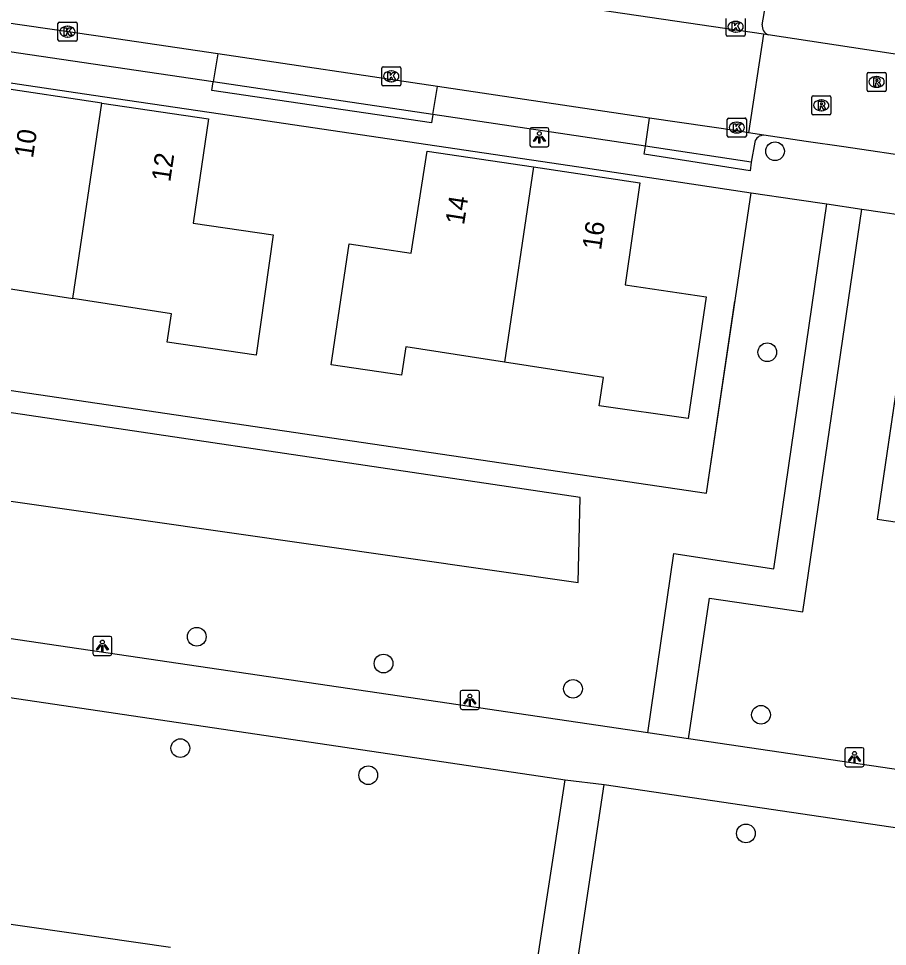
# Model space of a CAD drawing. Extents: x 164150 to 165261, y 382513 to 383432.
# Drawn here: x 164377.35 to 164422.79, y 383245.45 to 383293.97 of the extents above; entities that cross this region are included whole.
import ezdxf

# ---------------------------------------------------------------- set-up
doc = ezdxf.new("R2010")
doc.units = 0
for name, color, linetype in [('IMGEO_Boom', 7, 'Continuous'), ('IMGEO_Fietspad_gesloten', 7, 'Continuous'), ('IMGEO_Greppel_droge_sloot', 7, 'Continuous'), ('IMGEO_Groenvoorziening', 7, 'Continuous'), ('IMGEO_Hek', 7, 'Continuous'), ('IMGEO_Kolk', 7, 'Continuous'), ('IMGEO_Lichtpunt', 7, 'Continuous'), ('IMGEO_Pand', 7, 'Continuous'), ('IMGEO_Pand_nummerreeks', 7, 'Continuous'), ('IMGEO_Rijbaan_lokaal_open', 7, 'Continuous'), ('IMGEO_Rioolput', 7, 'Continuous'), ('IMGEO_Voetpad_gesloten', 7, 'Continuous'), ('IMGEO_Voetpad_open', 7, 'Continuous')]:
    doc.layers.add(name, color=color, linetype=linetype)

msp = doc.modelspace()

# ---------------------------------------------------------------- linework, layer by layer
at = {"layer": 'IMGEO_Boom'}
for centre in [(164416.91, 383287.031), (164416.506, 383276.521), (164386.67, 383261.645), (164396.438, 383260.244), (164406.346, 383258.921), (164416.177, 383257.562), (164385.811, 383255.821), (164395.639, 383254.405), (164415.388, 383251.362)]:
    msp.add_circle(centre, 0.489, dxfattribs=at)
at = {"layer": 'IMGEO_Fietspad_gesloten'}
for points in [[(164324.331, 383266.264), (164405.939, 383254.161)], [(164410.253, 383256.618), (164363.243, 383263.551)], [(164412.392, 383256.302), (164410.253, 383256.618)], [(164469.921, 383247.818), (164412.392, 383256.302)], [(164405.939, 383254.161), (164407.972, 383253.915)], [(164407.972, 383253.915), (164472.414, 383244.404)]]:
    msp.add_lwpolyline(points, dxfattribs=at)
at = {"layer": 'IMGEO_Greppel_droge_sloot'}
msp.add_lwpolyline([(164369.89, 383269.745), (164406.61, 383264.48), (164406.724, 383268.924), (164370.391, 383274.325)], dxfattribs=at)
at = {"layer": 'IMGEO_Groenvoorziening'}
for points in [[(164370.46, 383291.569), (164368.108, 383275.835), (164413.32, 383269.151), (164415.655, 383284.854)], [(164424.578, 383283.554), (164422.255, 383267.801), (164467.471, 383261.119), (164469.81, 383276.81)]]:
    msp.add_lwpolyline(points, dxfattribs=at)
at = {"layer": 'IMGEO_Hek'}
for points in [[(164369.61, 383285.882), (164368.108, 383275.835), (164413.32, 383269.151), (164414.814, 383279.195)], [(164423.736, 383277.843), (164422.255, 383267.801), (164467.471, 383261.119), (164468.968, 383271.158)]]:
    msp.add_lwpolyline(points, dxfattribs=at)
at = {"layer": 'IMGEO_Kolk'}
for p, q in [((164379.413, 383292.858), (164379.413, 383293.71)), ((164379.488, 383293.784), (164380.34, 383293.784)), ((164379.901, 383293.564), (164379.926, 383293.564)), ((164380.414, 383293.71), (164380.414, 383292.858)), ((164414.351, 383293.118), (164414.351, 383293.97)), ((164414.839, 383293.824), (164414.864, 383293.824)), ((164415.352, 383293.97), (164415.352, 383293.118)), ((164415.278, 383293.044), (164414.426, 383293.044)), ((164414.862, 383293.264), (164414.837, 383293.264)), ((164380.34, 383292.784), (164379.488, 383292.784)), ((164379.924, 383293.004), (164379.899, 383293.004)), ((164396.344, 383290.523), (164396.344, 383291.375)), ((164396.419, 383291.449), (164397.271, 383291.449)), ((164396.832, 383291.229), (164396.857, 383291.229)), ((164397.345, 383291.375), (164397.345, 383290.523)), ((164396.855, 383290.669), (164396.83, 383290.669)), ((164397.271, 383290.449), (164396.419, 383290.449)), ((164414.411, 383287.844), (164414.411, 383288.696)), ((164414.486, 383288.77), (164415.338, 383288.77)), ((164415.412, 383288.696), (164415.412, 383287.844)), ((164414.899, 383288.55), (164414.924, 383288.55)), ((164415.338, 383287.77), (164414.486, 383287.77)), ((164414.922, 383287.99), (164414.897, 383287.99))]:
    msp.add_line(p, q, dxfattribs=at)
for points in [[(164379.413, 383292.858), (164379.413, 383293.71)], [(164379.488, 383293.784), (164380.34, 383293.784)], [(164380.414, 383293.71), (164380.414, 383292.858)], [(164414.351, 383293.118), (164414.351, 383293.97)], [(164414.672, 383293.744), (164414.795, 383293.744), (164414.795, 383293.593), (164414.925, 383293.744), (164415.089, 383293.744), (164414.943, 383293.593), (164415.096, 383293.344), (164414.944, 383293.344), (164414.859, 383293.508), (164414.795, 383293.441), (164414.795, 383293.344), (164414.672, 383293.344), (164414.672, 383293.744)], [(164415.352, 383293.97), (164415.352, 383293.118)], [(164379.734, 383293.484), (164379.857, 383293.484), (164379.857, 383293.333), (164379.987, 383293.484), (164380.151, 383293.484), (164380.005, 383293.333), (164380.158, 383293.084), (164380.006, 383293.084), (164379.921, 383293.248), (164379.857, 383293.181), (164379.857, 383293.084), (164379.734, 383293.084), (164379.734, 383293.484)], [(164415.278, 383293.044), (164414.426, 383293.044)], [(164380.34, 383292.784), (164379.488, 383292.784)], [(164396.344, 383290.523), (164396.344, 383291.375)], [(164396.419, 383291.449), (164397.271, 383291.449)], [(164396.665, 383291.149), (164396.788, 383291.149), (164396.788, 383290.998), (164396.918, 383291.149), (164397.082, 383291.149), (164396.936, 383290.998), (164397.089, 383290.749), (164396.937, 383290.749), (164396.852, 383290.913), (164396.788, 383290.846), (164396.788, 383290.749), (164396.665, 383290.749), (164396.665, 383291.149)], [(164397.345, 383291.375), (164397.345, 383290.523)], [(164397.271, 383290.449), (164396.419, 383290.449)], [(164414.411, 383287.844), (164414.411, 383288.696)], [(164414.486, 383288.77), (164415.338, 383288.77)], [(164415.412, 383288.696), (164415.412, 383287.844)], [(164414.732, 383288.47), (164414.855, 383288.47), (164414.855, 383288.319), (164414.985, 383288.47), (164415.149, 383288.47), (164415.003, 383288.319), (164415.156, 383288.07), (164415.004, 383288.07), (164414.919, 383288.234), (164414.855, 383288.167), (164414.855, 383288.07), (164414.732, 383288.07), (164414.732, 383288.47)], [(164415.338, 383287.77), (164414.486, 383287.77)]]:
    msp.add_lwpolyline(points, dxfattribs=at)
for centre, start, end in [((164379.49, 383293.708), 91.552, 178.448), ((164379.49, 383293.708), 91.552, 178.448), ((164380.338, 383293.708), 1.552, 88.448), ((164380.338, 383293.708), 1.552, 88.448), ((164414.428, 383293.12), 181.552, 268.448), ((164414.428, 383293.12), 181.552, 268.448), ((164415.276, 383293.12), 271.552, 358.448), ((164415.276, 383293.12), 271.552, 358.448), ((164379.49, 383292.86), 181.552, 268.448), ((164379.49, 383292.86), 181.552, 268.448), ((164380.338, 383292.86), 271.552, 358.448), ((164380.338, 383292.86), 271.552, 358.448), ((164396.421, 383291.373), 91.552, 178.448), ((164396.421, 383291.373), 91.552, 178.448), ((164397.269, 383291.373), 1.552, 88.448), ((164397.269, 383291.373), 1.552, 88.448), ((164396.421, 383290.525), 181.552, 268.448), ((164396.421, 383290.525), 181.552, 268.448), ((164397.269, 383290.525), 271.552, 358.448), ((164397.269, 383290.525), 271.552, 358.448), ((164414.488, 383288.694), 91.552, 178.448), ((164414.488, 383288.694), 91.552, 178.448), ((164415.336, 383288.694), 1.552, 88.448), ((164415.336, 383288.694), 1.552, 88.448), ((164414.488, 383287.846), 181.552, 268.448), ((164414.488, 383287.846), 181.552, 268.448), ((164415.336, 383287.846), 271.552, 358.448), ((164415.336, 383287.846), 271.552, 358.448)]:
    msp.add_arc(centre, 0.0765, start, end, dxfattribs=at)
for centre, major_axis, ratio, start_param, end_param in [((164379.9, 383293.284), (-0.387, 0.002), 0.722429, 4.712389, 7.853982), ((164379.925, 383293.284), (-0.39, 0.002), 0.717154, 1.570796, 4.712389), ((164414.838, 383293.544), (-0.387, 0.002), 0.722429, 4.712389, 7.853982), ((164414.863, 383293.544), (-0.39, 0.002), 0.717154, 1.570796, 4.712389), ((164396.831, 383290.949), (-0.387, 0.002), 0.722429, 4.712389, 7.853982), ((164396.856, 383290.949), (-0.39, 0.002), 0.717154, 1.570796, 4.712389), ((164414.898, 383288.27), (-0.387, 0.002), 0.722429, 4.712389, 7.853982), ((164414.923, 383288.27), (-0.39, 0.002), 0.717154, 1.570796, 4.712389)]:
    msp.add_ellipse(centre, major_axis=major_axis, ratio=ratio, start_param=start_param, end_param=end_param, dxfattribs=at)
at = {"layer": 'IMGEO_Lichtpunt'}
for p, q in [((164404.991, 383288.258), (164404.183, 383288.258)), ((164404.991, 383288.258), (164404.183, 383288.258)), ((164404.089, 383288.163), (164404.089, 383287.356)), ((164404.089, 383288.163), (164404.089, 383287.356)), ((164405.085, 383287.356), (164405.085, 383288.163)), ((164405.085, 383287.356), (164405.085, 383288.163)), ((164404.183, 383287.262), (164404.991, 383287.262)), ((164404.183, 383287.262), (164404.991, 383287.262)), ((164381.237, 383261.571), (164381.237, 383260.764)), ((164381.237, 383261.571), (164381.237, 383260.764)), ((164382.139, 383261.666), (164381.331, 383261.666)), ((164382.139, 383261.666), (164381.331, 383261.666)), ((164382.233, 383260.764), (164382.233, 383261.571)), ((164382.233, 383260.764), (164382.233, 383261.571)), ((164381.331, 383260.67), (164382.139, 383260.67)), ((164381.331, 383260.67), (164382.139, 383260.67)), ((164400.452, 383258.745), (164400.452, 383257.938)), ((164400.452, 383258.745), (164400.452, 383257.938)), ((164401.354, 383258.84), (164400.546, 383258.84)), ((164401.354, 383258.84), (164400.546, 383258.84)), ((164401.448, 383257.938), (164401.448, 383258.745)), ((164401.448, 383257.938), (164401.448, 383258.745)), ((164400.546, 383257.844), (164401.354, 383257.844)), ((164400.546, 383257.844), (164401.354, 383257.844)), ((164420.567, 383255.749), (164420.567, 383254.942)), ((164420.567, 383255.749), (164420.567, 383254.942)), ((164421.469, 383255.844), (164420.661, 383255.844)), ((164421.469, 383255.844), (164420.661, 383255.844)), ((164421.563, 383254.942), (164421.563, 383255.749)), ((164421.563, 383254.942), (164421.563, 383255.749)), ((164420.661, 383254.848), (164421.469, 383254.848)), ((164420.661, 383254.848), (164421.469, 383254.848))]:
    msp.add_line(p, q, dxfattribs=at)
for points in [[(164404.463, 383287.827), (164404.502, 383287.799), (164404.314, 383287.537), (164404.276, 383287.564), (164404.463, 383287.827)], [(164404.565, 383287.779), (164404.612, 383287.779), (164404.612, 383287.457), (164404.565, 383287.457), (164404.565, 383287.779)], [(164404.675, 383287.799), (164404.713, 383287.826), (164404.9, 383287.564), (164404.861, 383287.536), (164404.675, 383287.799)], [(164381.611, 383261.235), (164381.65, 383261.207), (164381.462, 383260.945), (164381.424, 383260.972), (164381.611, 383261.235)], [(164381.713, 383261.187), (164381.76, 383261.187), (164381.76, 383260.865), (164381.713, 383260.865), (164381.713, 383261.187)], [(164381.823, 383261.207), (164381.861, 383261.234), (164382.048, 383260.972), (164382.009, 383260.944), (164381.823, 383261.207)], [(164400.826, 383258.409), (164400.865, 383258.381), (164400.677, 383258.119), (164400.639, 383258.146), (164400.826, 383258.409)], [(164400.928, 383258.361), (164400.975, 383258.361), (164400.975, 383258.039), (164400.928, 383258.039), (164400.928, 383258.361)], [(164401.038, 383258.381), (164401.076, 383258.408), (164401.263, 383258.146), (164401.224, 383258.118), (164401.038, 383258.381)], [(164420.941, 383255.413), (164420.98, 383255.385), (164420.792, 383255.123), (164420.754, 383255.15), (164420.941, 383255.413)], [(164421.043, 383255.365), (164421.09, 383255.365), (164421.09, 383255.043), (164421.043, 383255.043), (164421.043, 383255.365)], [(164421.153, 383255.385), (164421.191, 383255.412), (164421.378, 383255.15), (164421.339, 383255.122), (164421.153, 383255.385)]]:
    msp.add_lwpolyline(points, dxfattribs=at)
for centre in [(164404.588, 383287.961), (164381.736, 383261.369), (164400.951, 383258.543), (164421.066, 383255.547)]:
    msp.add_circle(centre, 0.0994, dxfattribs=at)
for centre, start, end in [((164404.183, 383288.163), 90, 180), ((164404.183, 383288.163), 90, 180), ((164404.991, 383288.163), 0, 90), ((164404.991, 383288.163), 0, 90), ((164404.183, 383287.356), 180, 270), ((164404.183, 383287.356), 180, 270), ((164404.991, 383287.356), 270, 0), ((164404.991, 383287.356), 270, 360), ((164381.331, 383261.571), 90, 180), ((164381.331, 383261.571), 90, 180), ((164382.139, 383261.571), 0, 90), ((164382.139, 383261.571), 0, 90), ((164381.331, 383260.764), 180, 270), ((164381.331, 383260.764), 180, 270), ((164382.139, 383260.764), 270, 0), ((164382.139, 383260.764), 270, 360), ((164400.546, 383258.745), 90, 180), ((164400.546, 383258.745), 90, 180), ((164401.354, 383258.745), 0, 90), ((164401.354, 383258.745), 0, 90), ((164400.546, 383257.938), 180, 270), ((164400.546, 383257.938), 180, 270), ((164401.354, 383257.938), 270, 0), ((164401.354, 383257.938), 270, 360), ((164420.661, 383255.749), 90, 180), ((164420.661, 383255.749), 90, 180), ((164421.469, 383255.749), 0, 90), ((164421.469, 383255.749), 0, 90), ((164420.661, 383254.942), 180, 270), ((164420.661, 383254.942), 180, 270), ((164421.469, 383254.942), 270, 0), ((164421.469, 383254.942), 270, 360)]:
    msp.add_arc(centre, 0.0946, start, end, dxfattribs=at)
at = {"layer": 'IMGEO_Pand'}
for points in [[(164381.713, 383289.549), (164376.135, 383290.377), (164375.336, 383285.025), (164371.093, 383285.661), (164370.154, 383279.333), (164374.793, 383278.644), (164375.013, 383280.128), (164380.196, 383279.324)], [(164380.196, 383279.324), (164381.713, 383289.549)], [(164381.713, 383289.549), (164387.291, 383288.721), (164386.484, 383283.271), (164390.673, 383282.655), (164389.771, 383276.371), (164385.129, 383277.04), (164385.343, 383278.525), (164380.196, 383279.324)], [(164402.764, 383276.006), (164397.602, 383276.808), (164397.382, 383275.324), (164393.699, 383275.871), (164394.636, 383282.183), (164397.89, 383281.695), (164398.723, 383287.041), (164404.283, 383286.214)], [(164404.283, 383286.214), (164409.843, 383285.386), (164409.065, 383280.045), (164413.304, 383279.419), (164412.36, 383273.05), (164407.718, 383273.72), (164407.932, 383275.204), (164402.764, 383276.006)], [(164404.283, 383286.214), (164402.764, 383276.006)], [(164372.462, 383247.267), (164385.296, 383245.41)]]:
    msp.add_lwpolyline(points, dxfattribs=at)
at = {"layer": 'IMGEO_Rijbaan_lokaal_open'}
for points in [[(164416.301, 383293.154), (164377.184, 383298.907)], [(164387.772, 383292.123), (164381.386, 383293.071), (164376.462, 383293.782)], [(164416.301, 383293.154), (164415.53, 383288.001)], [(164416.557, 383293.116), (164416.301, 383293.154)], [(164425.275, 383291.79), (164416.557, 383293.116)], [(164387.772, 383292.123), (164387.523, 383290.657)], [(164399.257, 383290.417), (164387.772, 383292.123)], [(164399.02, 383288.952), (164387.523, 383290.657)], [(164399.02, 383288.952), (164399.257, 383290.417)], [(164410.348, 383288.77), (164399.257, 383290.417)], [(164410.13, 383287.292), (164410.348, 383288.77)], [(164415.53, 383288.001), (164415.047, 383288.073), (164410.348, 383288.77)], [(164416.317, 383287.875), (164415.53, 383288.001)], [(164424.508, 383286.672), (164420.5, 383287.261), (164418.535, 383287.549), (164416.317, 383287.875)], [(164415.668, 383286.456), (164410.13, 383287.292)], [(164415.851, 383287.512), (164415.668, 383286.456)]]:
    msp.add_lwpolyline(points, dxfattribs=at)
msp.add_arc((164416.332, 383287.375), 0.501, 91.7674, 164.0677, dxfattribs=at)
at = {"layer": 'IMGEO_Rioolput'}
for p, q in [((164421.724, 383290.228), (164421.724, 383291.08)), ((164421.799, 383291.154), (164422.651, 383291.154)), ((164422.725, 383291.08), (164422.725, 383290.228)), ((164422.212, 383290.934), (164422.237, 383290.934)), ((164422.651, 383290.154), (164421.799, 383290.154)), ((164422.235, 383290.374), (164422.21, 383290.374)), ((164418.83, 383289.006), (164418.83, 383289.858)), ((164418.905, 383289.932), (164419.757, 383289.932)), ((164419.318, 383289.712), (164419.343, 383289.712)), ((164419.831, 383289.858), (164419.831, 383289.006)), ((164419.341, 383289.152), (164419.316, 383289.152)), ((164419.757, 383288.932), (164418.905, 383288.932))]:
    msp.add_line(p, q, dxfattribs=at)
for points in [[(164421.724, 383290.228), (164421.724, 383291.08)], [(164421.799, 383291.154), (164422.651, 383291.154)], [(164422.725, 383291.08), (164422.725, 383290.228)], [(164422.313, 383290.852), (164422.061, 383290.854), (164422.061, 383290.454)], [(164422.061, 383290.454), (164422.185, 383290.454), (164422.185, 383290.616), (164422.196, 383290.616)], [(164422.239, 383290.773), (164422.185, 383290.773), (164422.185, 383290.692)], [(164422.185, 383290.692), (164422.237, 383290.692)], [(164422.651, 383290.154), (164421.799, 383290.154)], [(164422.243, 383290.587), (164422.314, 383290.454), (164422.454, 383290.454), (164422.389, 383290.58)], [(164418.83, 383289.006), (164418.83, 383289.858)], [(164418.905, 383289.932), (164419.757, 383289.932)], [(164419.419, 383289.63), (164419.167, 383289.632), (164419.167, 383289.232)], [(164419.831, 383289.858), (164419.831, 383289.006)], [(164419.167, 383289.232), (164419.291, 383289.232), (164419.291, 383289.394), (164419.302, 383289.394)], [(164419.345, 383289.551), (164419.291, 383289.551), (164419.291, 383289.47)], [(164419.291, 383289.47), (164419.343, 383289.47)], [(164419.349, 383289.365), (164419.42, 383289.232), (164419.56, 383289.232), (164419.495, 383289.358)], [(164419.757, 383288.932), (164418.905, 383288.932)]]:
    msp.add_lwpolyline(points, dxfattribs=at)
for centre, radius, start, end in [((164421.801, 383291.078), 0.0765, 91.552, 178.448), ((164421.801, 383291.078), 0.0765, 91.552, 178.448), ((164422.649, 383291.078), 0.0765, 1.552, 88.448), ((164422.649, 383291.078), 0.0765, 1.552, 88.448), ((164422.195, 383290.563), 0.0533, 26.0293, 88.6989), ((164422.221, 383290.881), 0.19, 274.7715, 282.9687), ((164422.245, 383290.677), 0.0964, 77.0061, 93.1865), ((164422.259, 383290.734), 0.0378, 276.6634, 79.6772), ((164422.312, 383290.742), 0.109, 350.3612, 89.416), ((164422.31, 383290.742), 0.112, 277.5842, 350.9817), ((164422.294, 383290.527), 0.108, 29.5134, 73.7905), ((164421.801, 383290.23), 0.0765, 181.552, 268.448), ((164421.801, 383290.23), 0.0765, 181.552, 268.448), ((164422.649, 383290.23), 0.0765, 271.552, 358.448), ((164422.649, 383290.23), 0.0765, 271.552, 358.448), ((164418.907, 383289.856), 0.0765, 91.552, 178.448), ((164418.907, 383289.856), 0.0765, 91.552, 178.448), ((164419.418, 383289.52), 0.109, 350.3612, 89.416), ((164419.755, 383289.856), 0.0765, 1.552, 88.448), ((164419.755, 383289.856), 0.0765, 1.552, 88.448), ((164419.301, 383289.341), 0.0533, 26.0293, 88.6989), ((164419.327, 383289.659), 0.19, 274.7715, 282.9687), ((164419.351, 383289.455), 0.0964, 77.0061, 93.1865), ((164419.365, 383289.512), 0.0378, 276.6634, 79.6772), ((164419.416, 383289.52), 0.112, 277.5842, 350.9817), ((164419.4, 383289.305), 0.108, 29.5134, 73.7905), ((164418.907, 383289.008), 0.0765, 181.552, 268.448), ((164418.907, 383289.008), 0.0765, 181.552, 268.448), ((164419.755, 383289.008), 0.0765, 271.552, 358.448), ((164419.755, 383289.008), 0.0765, 271.552, 358.448)]:
    msp.add_arc(centre, radius, start, end, dxfattribs=at)
for centre, major_axis, ratio, start_param, end_param in [((164422.211, 383290.654), (-0.387, 0.002), 0.722429, 4.712389, 7.853982), ((164422.236, 383290.654), (-0.39, 0.002), 0.717154, 1.570796, 4.712389), ((164419.317, 383289.432), (-0.387, 0.002), 0.722429, 4.712389, 7.853982), ((164419.342, 383289.432), (-0.39, 0.002), 0.717154, 1.570796, 4.712389)]:
    msp.add_ellipse(centre, major_axis=major_axis, ratio=ratio, start_param=start_param, end_param=end_param, dxfattribs=at)
at = {"layer": 'IMGEO_Voetpad_gesloten'}
for points in [[(164410.253, 383256.618), (164411.617, 383265.999), (164416.841, 383265.204), (164419.619, 383284.276)], [(164412.392, 383256.302), (164413.479, 383263.66), (164418.361, 383262.942), (164421.456, 383284.009)], [(164419.619, 383284.276), (164421.456, 383284.009)], [(164404.121, 383242.364), (164405.939, 383254.161)], [(164406.195, 383242.078), (164407.972, 383253.915)]]:
    msp.add_lwpolyline(points, dxfattribs=at)
at = {"layer": 'IMGEO_Voetpad_open'}
for points in [[(164416.242, 383293.649), (164416.41, 383294.636)], [(164387.523, 383290.657), (164381.248, 383291.584), (164376.884, 383292.237)], [(164370.46, 383291.569), (164381.278, 383289.967), (164387.313, 383289.078), (164406.647, 383286.21), (164415.655, 383284.854)], [(164399.02, 383288.952), (164398.95, 383288.512), (164387.453, 383290.216), (164387.523, 383290.657)], [(164410.13, 383287.292), (164399.02, 383288.952)], [(164415.668, 383286.456), (164415.608, 383286.007), (164410.059, 383286.875), (164410.13, 383287.292)], [(164415.655, 383284.854), (164418.056, 383284.504), (164419.619, 383284.276)], [(164421.456, 383284.009), (164424.578, 383283.554)]]:
    msp.add_lwpolyline(points, dxfattribs=at)
msp.add_arc((164416.732, 383293.579), 0.495, 171.876, 249.2897, dxfattribs=at)

# ---------------------------------------------------------------- texts
at = {"layer": 'IMGEO_Pand_nummerreeks'}
for s, rotation, p in [('10', 81.5122, (164378.104, 383286.634)), ('12', 81.5739, (164385.282, 383285.395)), ('14', 81.137, (164400.646, 383283.144)), ('16', 81.7106, (164407.809, 383281.827))]:
    msp.add_text(s, height=1, rotation=rotation, dxfattribs=at).set_placement(p)

doc.saveas('drawing.dxf')
